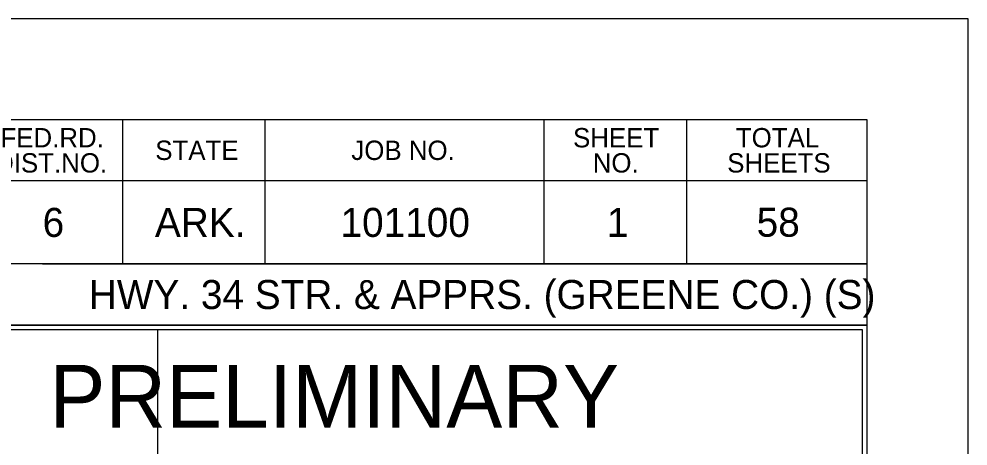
# Model space of a CAD drawing. Extents: x -0.3 to 2.65, y 0 to 1.9.
# Drawn here: x 1.2203 to 1.4167, y 0.8284 to 0.9167 of the extents above; entities that cross this region are included whole.
import ezdxf

# ---------------------------------------------------------------- set-up
doc = ezdxf.new("R2010")
doc.units = 0
for name, color, linetype in [('Level 8', 7, 'Continuous'), ('Level 9', 7, 'Continuous'), ('SHET_Annotations', 7, 'Continuous'), ('SHET_Border-Lines', 7, 'Continuous'), ('SHET_Border-Text', 7, 'Continuous')]:
    doc.layers.add(name, color=color, linetype=linetype)

msp = doc.modelspace()

# ---------------------------------------------------------------- linework, layer by layer
at = {"layer": 'Level 8'}
msp.add_lwpolyline([(1.249, 0.70571), (1.39483, 0.70571), (1.39483, 0.85238), (1.249, 0.85238)], close=True, dxfattribs=at)
at = {"layer": 'Level 9'}
msp.add_lwpolyline([(1.21366, 0.81193), (1.39483, 0.81193), (1.39483, 0.85238), (1.21366, 0.85238)], close=True, dxfattribs=at)
at = {"layer": 'SHET_Border-Lines'}
for p, q in [((1.24173, 0.89583), (1.24173, 0.86601)), ((1.27123, 0.89583), (1.27123, 0.86601)), ((1.32894, 0.89583), (1.32894, 0.86601)), ((1.35843, 0.89583), (1.35843, 0.86601)), ((1.39583, 0.8832), (1.21266, 0.8832)), ((1.39583, 0.88329), (1.39583, 0.88329)), ((1.39583, 0.86601), (1.21266, 0.86601)), ((1.22524, 0.86601), (1.39583, 0.86601)), ((1.39583, 0.85338), (1.12962, 0.85338))]:
    msp.add_line(p, q, dxfattribs=at)
for points in [[(0, 0), (1.41667, 0), (1.41667, 0.91667), (0, 0.91667)], [(0.02083, 0.02083), (1.39583, 0.02083), (1.39583, 0.89583), (0.02083, 0.89583)], [(1.12962, 0.85338), (1.39583, 0.85338), (1.39583, 0.89583), (1.12962, 0.89583)]]:
    msp.add_lwpolyline(points, close=True, dxfattribs=at)

# ---------------------------------------------------------------- texts
at = {"layer": 'Level 9'}
msp.add_text('PRELIMINARY', height=0.013, dxfattribs=at).set_placement((1.22663, 0.83215))
at = {"layer": 'SHET_Annotations'}
for s, p in [('6', (1.22524, 0.87161)), ('ARK.', (1.24847, 0.87161)), ('101100', (1.28686, 0.87161)), ('1', (1.34195, 0.87161)), ('58', (1.37294, 0.87165)), (' HWY. 34 STR. & APPRS. (GREENE CO.) (S)', (1.23257, 0.8567))]:
    msp.add_text(s, height=0.006, dxfattribs=at).set_placement(p)
at = {"layer": 'SHET_Border-Text'}
for s, p in [('FED.RD.', (1.21651, 0.89012)), ('SHEET', (1.33496, 0.89012)), ('TOTAL', (1.36864, 0.89012)), ('STATE', (1.24854, 0.88752)), ('JOB NO.', (1.2891, 0.88752)), ('DIST.NO.', (1.21541, 0.88492)), ('NO.', (1.33903, 0.88492)), ('SHEETS', (1.36685, 0.88492))]:
    msp.add_text(s, height=0.004, dxfattribs=at).set_placement(p)

doc.saveas('drawing.dxf')
